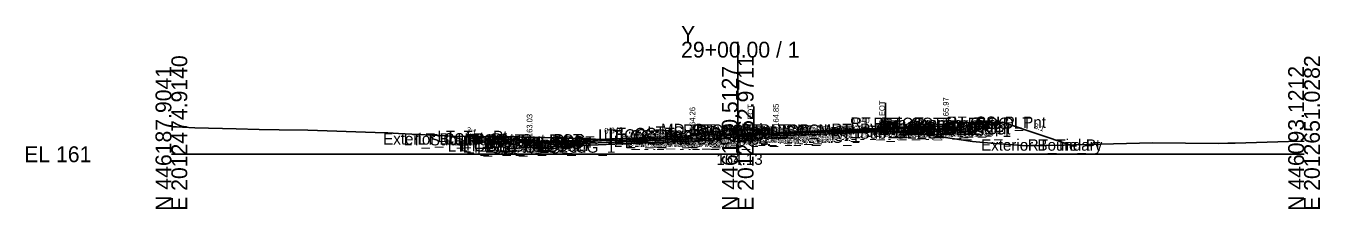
# Model space of a CAD drawing. Extents: x -26 to 3203, y -10 to 9532.
# Drawn here: x 1974.3 to 2202.8, y 2990.3 to 3022.7 of the extents above; entities that cross this region are included whole.
import ezdxf

# ---------------------------------------------------------------- set-up
doc = ezdxf.new("R2010")
doc.units = 0
for name, color, linetype in [('Default', 7, 'Continuous'), ('Exist CMT Pavement', 7, 'Continuous'), ('Exist Cross Section Cell', 7, 'Continuous'), ('Exist XS Center Line Elevation Label', 7, 'Continuous'), ('Exist XS Ground Line', 7, 'Continuous'), ('Prop CMT Conc Surface', 7, 'Continuous'), ('Prop CMT Concrete Structures', 7, 'Continuous'), ('Prop CMT Pvmt Course 1', 7, 'Continuous'), ('Prop CMT Pvmt Course 1 CG', 7, 'Continuous'), ('Prop CMT Pvmt Course 2', 7, 'Continuous'), ('Prop CMT Pvmt Course 2 Wedge', 7, 'Continuous'), ('Prop CMT Pvmt Course 3', 7, 'Continuous'), ('Prop CMT Pvmt Surface', 7, 'Continuous'), ('Prop CMT Pvmt Wedge Surface 3', 7, 'Continuous'), ('Prop CMT Slope Grass', 7, 'Continuous'), ('Prop CMT Subgrade Earthwork', 7, 'Continuous'), ('Prop XS Hydro Elevations', 7, 'Continuous'), ('Prop XS Label Text', 7, 'Continuous'), ('Prop XS SE Text', 7, 'Continuous'), ('Prop XS Side Slope Text', 7, 'Continuous'), ('Scratch_Level_0', 7, 'Continuous')]:
    doc.layers.add(name, color=color, linetype=linetype)

msp = doc.modelspace()

# ---------------------------------------------------------------- linework, layer by layer
at = {"layer": 'Exist CMT Pavement'}
msp.add_lwpolyline([(2102.86, 3003.45), (2103.2, 3003.46), (2104.6, 3003.51), (2105.18, 3003.54), (2106.26, 3003.59), (2107.46, 3003.65), (2108.83, 3003.7), (2110.27, 3003.75), (2111.52, 3003.79), (2112.56, 3003.82), (2113.13, 3003.85), (2114.69, 3003.91), (2115.61, 3003.93), (2115.94, 3003.94), (2116.77, 3003.95), (2118.76, 3003.99), (2121.07, 3004.03), (2122.05, 3004.05), (2123.6, 3004.06), (2124.45, 3004.07), (2125.53, 3004.08), (2126.09, 3004.09), (2126.09, 3004.09)], dxfattribs=at)
at = {"layer": 'Exist Cross Section Cell'}
for p, q in [((2100, 3000), (2100, 3019.88)), ((2000, 3000), (2100, 3000)), ((2100, 3000), (2200, 3000))]:
    msp.add_line(p, q, dxfattribs=at)
at = {"layer": 'Exist XS Ground Line'}
msp.add_lwpolyline([(2000, 3004.84), (2000.91, 3004.83), (2001.97, 3004.77), (2004.15, 3004.68), (2011.42, 3004.5), (2015.51, 3004.36), (2019.01, 3004.32), (2024.12, 3004.23), (2036.01, 3003.86), (2038.22, 3003.77), (2040.12, 3003.67), (2049.58, 3003.2), (2060.6, 3003.07), (2061.28, 3003.06), (2071.86, 3002.76), (2076.41, 3002.58), (2083.78, 3002.06), (2085.97, 3002), (2087.99, 3002.13), (2095.89, 3002.54), (2100, 3003.13), (2100.54, 3003.21), (2101.61, 3003.38), (2102.27, 3003.42), (2102.86, 3003.45), (2103.2, 3003.46), (2104.6, 3003.51), (2105.18, 3003.54), (2106.26, 3003.59), (2107.46, 3003.65), (2108.83, 3003.7), (2110.27, 3003.75), (2111.52, 3003.79), (2112.56, 3003.82), (2113.13, 3003.85), (2114.69, 3003.91), (2115.61, 3003.93), (2115.94, 3003.94), (2116.77, 3003.95), (2118.76, 3003.99), (2121.07, 3004.03), (2122.05, 3004.05), (2123.6, 3004.06), (2124.45, 3004.07), (2125.53, 3004.08), (2126.09, 3004.09), (2126.87, 3004.09), (2127.29, 3004.09), (2129.38, 3003.9), (2130.36, 3003.81), (2132.11, 3003.65), (2134.67, 3003.25), (2141.43, 3002.24), (2145.43, 3001.91), (2151.07, 3001.5), (2157.64, 3001.6), (2166.36, 3001.85), (2173.23, 3002.02), (2184.92, 3001.92), (2186.56, 3001.94), (2187.84, 3001.98), (2197.23, 3002.23), (2200, 3002.3)], dxfattribs=at)
at = {"layer": 'Prop CMT Conc Surface'}
for points in [[(2136.75, 3004.97), (2136.75, 3005.47), (2137.25, 3005.47)], [(2141.25, 3005.56), (2146.25, 3005.66)], [(2091.25, 3003.23), (2092, 3003.26), (2092, 3003.42), (2092.76, 3003.67)], [(2108.75, 3003.93), (2106.75, 3003.85), (2106.75, 3004.01), (2106, 3004.26)], [(2134.75, 3004.97), (2136.75, 3004.97)], [(2058.75, 3002.62), (2053.75, 3002.72)], [(2063.25, 3002.03), (2063.25, 3002.53), (2062.75, 3002.53)], [(2065.25, 3002.19), (2063.25, 3002.03)]]:
    msp.add_lwpolyline(points, dxfattribs=at)
at = {"layer": 'Prop CMT Concrete Structures'}
for points in [[(2134.75, 3004.97), (2136.75, 3004.97), (2136.75, 3005.47), (2137.25, 3005.47)], [(2137.25, 3005.47), (2137.25, 3004.48), (2134.75, 3004.38)], [(2146.25, 3005.66), (2141.25, 3005.56)], [(2141.25, 3005.56), (2141.25, 3005.22)], [(2141.25, 3005.22), (2146.25, 3005.32)], [(2146.25, 3005.32), (2146.25, 3005.66)], [(2091.25, 3003.23), (2092, 3003.26), (2092, 3003.42), (2092.76, 3003.67)], [(2091.25, 3002.64), (2091.25, 3003.23)], [(2092.76, 3003.67), (2092.76, 3002.7)], [(2108.75, 3003.93), (2106.75, 3003.85), (2106.75, 3004.01), (2106, 3004.26)], [(2106, 3004.26), (2106, 3003.23)], [(2106, 3003.23), (2108.75, 3003.34)], [(2108.75, 3003.34), (2108.75, 3003.93)], [(2134.75, 3004.38), (2134.75, 3004.97)], [(2053.75, 3002.38), (2053.75, 3002.72)], [(2053.75, 3002.72), (2058.75, 3002.62)], [(2058.75, 3002.28), (2053.75, 3002.38)], [(2058.75, 3002.62), (2058.75, 3002.28)], [(2065.25, 3002.19), (2063.25, 3002.03), (2063.25, 3002.53), (2062.75, 3002.53)], [(2062.75, 3002.53), (2062.75, 3001.5), (2065.25, 3001.6)], [(2065.25, 3001.6), (2065.25, 3002.19)], [(2092.76, 3002.7), (2091.25, 3002.64)]]:
    msp.add_lwpolyline(points, dxfattribs=at)
at = {"layer": 'Prop CMT Pvmt Course 1'}
for points in [[(2091.25, 3003.23), (2065.25, 3002.19)], [(2065.25, 3001.94), (2091.25, 3002.98)], [(2091.25, 3002.98), (2091.25, 3003.23)], [(2091.25, 3002.98), (2091.25, 3002.98), (2091.25, 3002.98)], [(2108.75, 3003.93), (2134.75, 3004.97)], [(2134.75, 3004.72), (2127.29, 3004.42), (2108.75, 3003.68)], [(2108.75, 3003.68), (2108.75, 3003.93)], [(2108.75, 3003.68), (2108.75, 3003.68)], [(2134.75, 3004.97), (2134.75, 3004.72)], [(2065.25, 3002.19), (2065.25, 3001.94)]]:
    msp.add_lwpolyline(points, dxfattribs=at)
at = {"layer": 'Prop CMT Pvmt Course 1 CG'}
for points in [[(2108.75, 3003.34), (2105.5, 3003.21), (2105.15, 3002.87)], [(2105.15, 3002.87), (2108.75, 3003.01)], [(2108.75, 3003.01), (2108.75, 3003.34)], [(2134.75, 3004.38), (2137.75, 3004.5), (2138.07, 3004.18)], [(2134.75, 3004.05), (2134.75, 3004.38)], [(2138.07, 3004.18), (2134.75, 3004.05)], [(2065.25, 3001.6), (2062.25, 3001.48), (2061.9, 3001.14)], [(2061.9, 3001.14), (2065.25, 3001.27)], [(2065.25, 3001.27), (2065.25, 3001.6)], [(2091.25, 3002.64), (2093.26, 3002.72), (2093.58, 3002.4)], [(2091.25, 3002.31), (2091.25, 3002.64)], [(2093.58, 3002.4), (2091.25, 3002.31)]]:
    msp.add_lwpolyline(points, dxfattribs=at)
at = {"layer": 'Prop CMT Pvmt Course 2'}
for points in [[(2091.25, 3002.98), (2065.25, 3001.94)], [(2091.25, 3002.64), (2091.25, 3002.98)], [(2108.75, 3003.68), (2108.75, 3003.68)], [(2126.09, 3004.37), (2134.75, 3004.72)], [(2134.75, 3004.38), (2126.09, 3004.04)], [(2126.09, 3004.04), (2126.09, 3004.37)], [(2134.75, 3004.72), (2134.75, 3004.38)], [(2065.25, 3001.6), (2091.25, 3002.64)], [(2065.25, 3001.94), (2065.25, 3001.6)]]:
    msp.add_lwpolyline(points, dxfattribs=at)
msp.add_lwpolyline([(2108.75, 3003.68), (2108.75, 3003.34), (2108.75, 3003.34)], close=True, dxfattribs=at)
at = {"layer": 'Prop CMT Pvmt Course 2 Wedge'}
msp.add_lwpolyline([(2108.75, 3003.68), (2126.09, 3004.37)], dxfattribs=at)
at = {"layer": 'Prop CMT Pvmt Course 3'}
for points in [[(2108.75, 3003.34), (2108.75, 3003.34), (2108.75, 3003.01), (2108.75, 3003.01)], [(2108.75, 3003.01), (2108.75, 3003.34)], [(2126.09, 3004.04), (2134.75, 3004.38)], [(2134.75, 3004.05), (2126.09, 3003.7)], [(2126.09, 3003.7), (2126.09, 3004.04)], [(2134.75, 3004.38), (2134.75, 3004.05)], [(2091.25, 3002.64), (2065.25, 3001.6)], [(2065.25, 3001.27), (2091.25, 3002.31)], [(2065.25, 3001.6), (2065.25, 3001.27)], [(2091.25, 3002.31), (2091.25, 3002.64)]]:
    msp.add_lwpolyline(points, dxfattribs=at)
at = {"layer": 'Prop CMT Pvmt Surface'}
for points in [[(2091.25, 3003.23), (2065.25, 3002.19)], [(2108.75, 3003.93), (2134.75, 3004.97)]]:
    msp.add_lwpolyline(points, dxfattribs=at)
at = {"layer": 'Prop CMT Pvmt Wedge Surface 3'}
msp.add_lwpolyline([(2108.75, 3003.34), (2134.75, 3004.38)], dxfattribs=at)
at = {"layer": 'Prop CMT Slope Grass'}
for points in [[(2137.25, 3005.47), (2146.75, 3005.66)], [(2146.75, 3005.66), (2158.83, 3001.63)], [(2053.25, 3002.72), (2051.87, 3003.18)], [(2092.76, 3003.67), (2099.38, 3004.39)], [(2106, 3004.26), (2099.38, 3004.39)], [(2062.75, 3002.53), (2053.25, 3002.72)]]:
    msp.add_lwpolyline(points, dxfattribs=at)
at = {"layer": 'Prop CMT Subgrade Earthwork'}
for points in [[(2134.75, 3004.05), (2138.07, 3004.18), (2139.4, 3005.51)], [(2095.11, 3003.93), (2093.58, 3002.4)], [(2103.71, 3004.31), (2105.15, 3002.87)], [(2105.15, 3002.87), (2108.75, 3003.01)], [(2108.75, 3003.01), (2108.73, 3003.69)], [(2108.75, 3003.01), (2108.75, 3003.01)], [(2108.75, 3003.01), (2108.75, 3003.01)], [(2126.09, 3003.7), (2126.11, 3004.07)], [(2126.09, 3003.7), (2134.75, 3004.05)], [(2134.75, 3004.05), (2134.75, 3004.05)], [(2065.25, 3001.27), (2061.9, 3001.14), (2060.47, 3002.57)], [(2091.25, 3002.31), (2065.25, 3001.27)], [(2065.25, 3001.27), (2065.25, 3001.27)], [(2093.58, 3002.4), (2091.25, 3002.31)], [(2091.25, 3002.31), (2091.25, 3002.31)], [(2091.25, 3002.31), (2091.25, 3002.31)]]:
    msp.add_lwpolyline(points, dxfattribs=at)
at = {"layer": 'Prop XS Label Text'}
for p, q in [((2102.86, 3008.45), (2102.86, 3003.45)), ((2126.09, 3009.09), (2126.09, 3004.09))]:
    msp.add_line(p, q, dxfattribs=at)

# ---------------------------------------------------------------- texts
at = {"layer": 'Default'}
msp.add_text('-', height=0.0001, dxfattribs=at).set_placement((2000, 3000))
at = {"layer": 'Exist Cross Section Cell'}
for s, p in [('Y', (2090, 3019.88)), ('29+00.00 / 1', (2090, 3017.08)), ('EL 161', (1974, 2998.6))]:
    msp.add_text(s, height=2.8, dxfattribs=at).set_placement(p)
for s, p in [('E 2012474.9140', (2002.8, 2990)), ('E 2012562.9711', (2102.8, 2990)), ('E 2012651.0282', (2202.8, 2990)), ('N 446187.9041', (2000, 2990)), ('N 446140.5127', (2100, 2990)), ('N 446093.1212', (2200, 2990))]:
    msp.add_text(s, height=2.8, rotation=90, dxfattribs=at).set_placement(p)
at = {"layer": 'Exist XS Center Line Elevation Label'}
msp.add_text('164.13', height=2, dxfattribs=at).set_placement((2096.23, 2998.13))
at = {"layer": 'Prop XS Hydro Elevations'}
for s, p in [('165.97', (2137.25, 3005.97)), ('164.26', (2092.5, 3004.26)), ('164.85', (2107.25, 3004.85)), ('163.03', (2063.75, 3003.03))]:
    msp.add_text(s, height=1, rotation=90, dxfattribs=at).set_placement(p)
at = {"layer": 'Prop XS Label Text'}
for p in [(2102.76, 3004.47), (2125.99, 3005.11)]:
    msp.add_text('E. EOT', height=1, rotation=90, dxfattribs=at).set_placement(p)
at = {"layer": 'Prop XS SE Text'}
for p in [(2119.96, 3005.38), (2076.46, 3003.64)]:
    msp.add_text('0.040', height=1, rotation=2.2906, dxfattribs=at).set_placement(p)
at = {"layer": 'Prop XS Side Slope Text'}
for p in [(2152.21, 3004.58), (2051.97, 3003.93)]:
    msp.add_text('3:1', height=1, rotation=341.5651, dxfattribs=at).set_placement(p)
at = {"layer": 'Scratch_Level_0'}
for s, p in [('MD_Crown Point', (2086.45, 3003.39)), ('RT_CG_Top_BOC_Med', (2090.35, 3003.26)), ('RT_CG_Top_BOC In', (2091.97, 3003.26)), ('RT_Sub_DLT_In', (2092.61, 3003.31)), ('RT_PV2_OEEOP', (2116.55, 3003.42)), ('RT_Sub_Trench_Out_DLT', (2119.92, 3004.51)), ('RT_CG_Top_Face', (2123.96, 3004.47)), ('RT_CG1_Shelf_Out', (2124.25, 3003.5)), ('RT_CG_Bot_IE', (2124.62, 3003.38)), ('RT_PV2_OEOT', (2124.88, 3003.72)), ('RT_PV3_OEOT', (2124.88, 3003.38)), ('RT_CG_Top_Gut', (2124.94, 3003.97)), ('RT_PV1_OEOT', (2125.44, 3003.97)), ('RT_CG_Top_BOC', (2125.49, 3004.47)), ('RT_CG_Bot_BOC', (2125.52, 3003.48)), ('RT_Sub_OEOP', (2128.13, 3003.18)), ('RT_CSLP_Pnt', (2136.88, 3004.66)), ('Exterior Boundary', (2037.39, 3001.72)), ('LT_Sub_Trench_Out_DLT', (2041.03, 3001.57)), ('LT_CSLP_Pnt', (2043.42, 3001.72)), ('LT_Tie_Pt', (2046.98, 3002.15)), ('LT_CG_Top_Face', (2050.51, 3001.53)), ('LT_CG_Top_BOC', (2051.03, 3001.53)), ('LT_CG_Top_Gut', (2051.49, 3001.03)), ('LT_PV2_OEOT', (2055.42, 3000.94)), ('LT_PV1_OEOT', (2055.99, 3001.19)), ('LT_CG_Top_Face_Med', (2075.37, 3002.42)), ('LT_CG_Top_Gut_Med', (2076.35, 3002.26)), ('LT_CG_Top_BOC_Med', (2077.15, 3002.67)), ('LT_CG_Bot_BOC_Med', (2077.19, 3001.7)), ('LT_CG_Bot_IE_Med', (2077.31, 3001.64)), ('LT_Sub_IEOT_CG_1', (2078.12, 3001.31)), ('LT_Sub_OEEOP', (2080.46, 3001.31)), ('LT_PV2_OEEOP', (2080.56, 3001.98)), ('LT_PV3_OEEOP', (2080.56, 3001.64)), ('LT_Sub_IEEOP', (2081.11, 3001.31)), ('LT_PV2_IEEOP', (2081.2, 3001.98)), ('LT_CG1_Shelf_In', (2081.43, 3001.72)), ('LT_Sub_PGL', (2082.37, 3001.31)), ('LT_PV2_PGL', (2082.46, 3001.98)), ('LT_PV1_PGL', (2083.03, 3002.23)), ('LT_Sub_DLT_In', (2084.05, 3002.93)), ('LT_Sub_IEOP', (2084.34, 3001.4)), ('RT_CG_Bot BOC In', (2091.84, 3002.23)), ('RT_CG_Top FOC In', (2092.61, 3003.01)), ('RT_CG_Top_Gut In', (2092.64, 3002.85)), ('RT_CG1_Shelf_In', (2093.63, 3002.21)), ('RT_CG_Bot_IE_Med', (2094.77, 3002.34)), ('RT_PV_Sub_Tie_In', (2095.25, 3002.69)), ('RT_Sub_IEOT_CG_1', (2095.57, 3002.01)), ('RT_Sub_IEOP', (2095.86, 3001.87)), ('RT_PV_IEEOP_EG', (2096.89, 3002.7)), ('RT_Sub_IEEOP', (2098.56, 3002.01)), ('RT_PV2_IEEOP', (2098.66, 3002.68)), ('RT_PV3_IEEOP', (2098.66, 3002.34)), ('RT_Sub_PGL', (2099.82, 3002.01)), ('RT_PV2_PGL', (2099.92, 3002.68)), ('RT_PV3_PGL', (2099.92, 3002.34)), ('RT_PV1_PGL', (2100.48, 3002.93)), ('RT_PV_Sub_Tie_Out', (2112.2, 3003.09)), ('RT_PV_OEEOP_EG', (2114.78, 3003.09)), ('RT_Sub_OEEOP', (2116.45, 3002.75)), ('RT_PV3_OEEOP', (2116.55, 3003.08)), ('RT_Sub_OEOT_CG_1', (2120.92, 3003.05)), ('RT_Sub_OEOT', (2124.78, 3003.05)), ('LT_CG1_Shelf_Out', (2048.8, 3000.48)), ('LT_CG_Bot_BOC', (2051.06, 3000.5)), ('LT_Sub_OEOT_CG_1', (2051.47, 3000.27)), ('LT_Sub_OEOP', (2052.01, 3000.14)), ('LT_CG_Bot_IE', (2055.16, 3000.6)), ('LT_Sub_OEOT', (2055.33, 3000.27)), ('LT_PV3_OEOT', (2055.42, 3000.6)), ('Exterior Boundary', (2142.97, 3000.63)), ('RT_Tie_Pt', (2151.22, 3000.63))]:
    msp.add_text(s, height=2, dxfattribs=at).set_placement(p)

doc.saveas('drawing.dxf')
